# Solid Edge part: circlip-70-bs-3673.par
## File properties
Title: External circlip for shaft Ø70 - BS 3673
Author: TraceParts S.A.
Template: Iso Metric Part.par
Last saved by: Nimesh.N
Revision: 4
Application: TraceParts
Company: TraceParts S.A.
Density: 7833.000 kg/m^3
Accuracy: 0.990
REFERENCE: BS 3673 - d 70 - d2 67
STANDARD: BS 3673
DESIGN: External circlip for shaft Ø70 - BS 3673
OMNICLASS23: 23.13.23.11.13.25
TraceParts.PartStandardAcronym: BS
TraceParts.PartStatus: Published
TraceParts.PartNumber: 10-08012002-076217
TraceParts.InstanceId: 10-08012002-0762173ILZ6QTHQZ0MXQC2MH7NX9D0J
TraceParts.PartLanguage: en
TraceParts.PartTitle: External circlip
TraceParts.PartVersion: 1.3.0
TRACEPARTS: TRACEPARTS
TraceParts.ClassPath: BS:10-08012002-076217
Username: Nimesh.N
Material: Steel
Face Style: Bronze (aged)
Fill Style: ANSI32(Steel)
Virtual Style: ANSI32(Steel)
Grouping: Metals\Steel
LibraryName: Materials
Coef. of Thermal Exp: 1.3e-05
Thermal Conductivity: 32.0
Specific Heat: 481.0
Modulus of Elasticity: 199947953000.0
Poisson's Ratio: 0.29
Yield Stress: 262000766.0
Ultimate Stress: 358527364.0
Elongation: 0.0
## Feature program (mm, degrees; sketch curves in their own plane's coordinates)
body "unnamed Body 1"
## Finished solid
Body 1: solid body, 16 faces, 40 edges, 28 vertices.
  Faces by surface: cylinder 8, plane 8
  Edges by curve: line 24, circle 16
Bounding box of the edges (mm): 75.800 x 81.710 x 2.500, from (-37.9, -41.61, 0) to (37.9, 40.1, 2.5).
Cylindrical faces by radius (mm): R1.5 x2, R4.2117 x4, R33.5 x1, R37.9 x1
Planar faces by outward normal: +x 2, +z 1, -x 2, -y 2, -z 1
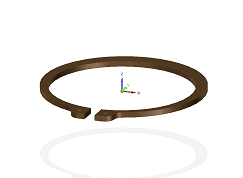
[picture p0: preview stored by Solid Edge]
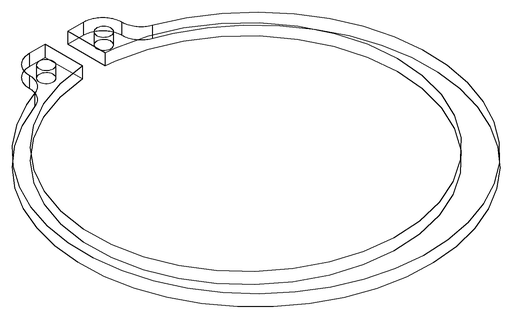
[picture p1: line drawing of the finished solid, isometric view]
